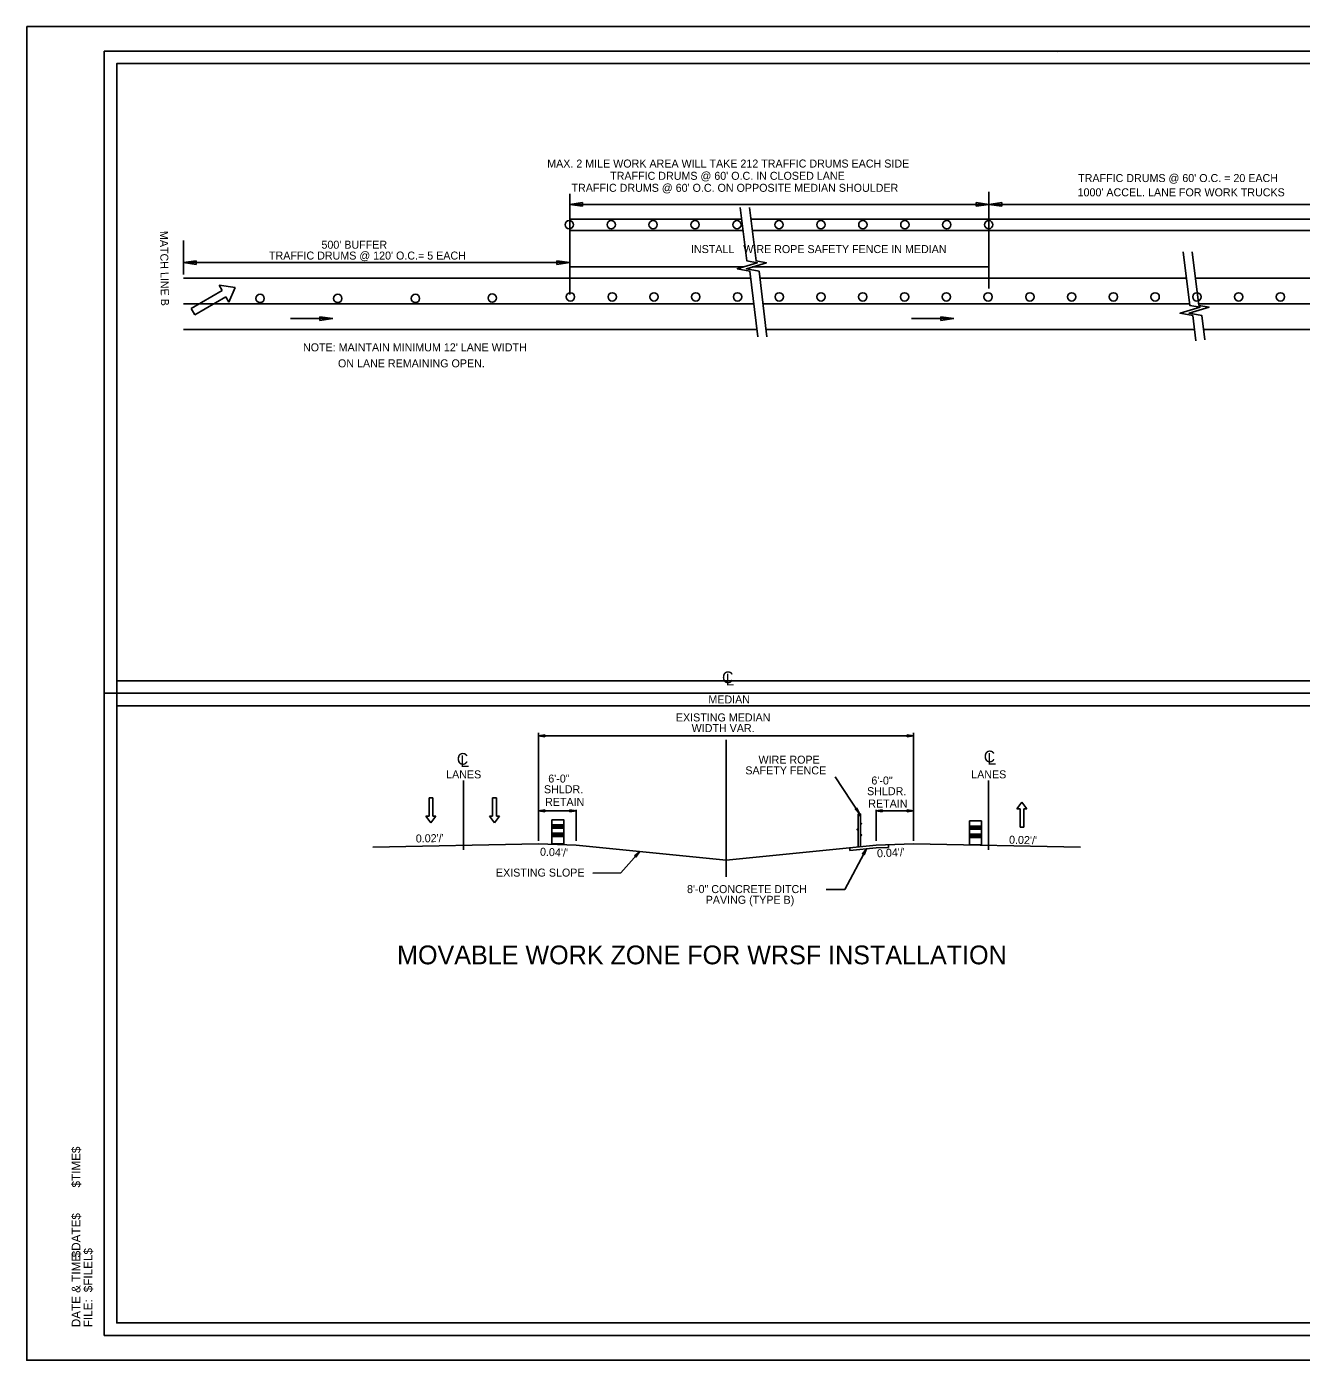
# Model space of a CAD drawing. Extents: x 1373222 to 1374279, y 380783 to 380996.
# Drawn here: x 1373945.4 to 1374149.3, y 380783.1 to 380996.5 of the extents above; entities that cross this region are included whole.
import ezdxf

# ---------------------------------------------------------------- set-up
doc = ezdxf.new("R2010")
doc.units = 0
for name, color, linetype in [('R_Border', 7, 'Continuous'), ('R_Border Notes', 7, 'Continuous'), ('R_Border Plan-Plan', 7, 'Continuous'), ('R_Draft', 7, 'Continuous'), ('R_No Plot', 7, 'Continuous')]:
    doc.layers.add(name, color=color, linetype=linetype)

msp = doc.modelspace()

# ---------------------------------------------------------------- linework, layer by layer
at = {"layer": 'R_Border'}
for p, q in [((1373957.81, 380992.59), (1374273.99, 380992.59)), ((1373957.81, 380787.13), (1373957.81, 380992.59)), ((1374110.33, 380992.33), (1374110.33, 380992.33)), ((1374110.33, 380992.33), (1374110.33, 380992.33)), ((1373957.81, 380787.13), (1373957.81, 380787.13)), ((1374273.99, 380787.13), (1373957.81, 380787.13))]:
    msp.add_line(p, q, dxfattribs=at)
at = {"layer": 'R_Border Plan-Plan'}
msp.add_line((1373957.81, 380889.86), (1374273.99, 380889.86), dxfattribs=at)
at = {"layer": 'R_Draft'}
for p, q in [((1374032.3, 380969.76), (1374032.3, 380953.63)), ((1374099.37, 380970.08), (1374099.37, 380954.63)), ((1374032.3, 380968.06), (1374034.36, 380968.37)), ((1374099.37, 380968.06), (1374032.3, 380968.06)), ((1374034.36, 380967.75), (1374032.3, 380968.06)), ((1374034.36, 380968.37), (1374034.36, 380967.75)), ((1374097.31, 380967.75), (1374097.31, 380968.37)), ((1374097.31, 380968.37), (1374099.37, 380968.06)), ((1374099.37, 380968.06), (1374097.31, 380967.75)), ((1374099.37, 380968.06), (1374101.43, 380968.37)), ((1374161.19, 380968.06), (1374099.37, 380968.06)), ((1374101.43, 380967.75), (1374099.37, 380968.06)), ((1374101.43, 380968.37), (1374101.43, 380967.75)), ((1374032.3, 380965.67), (1374059.82, 380965.67)), ((1374061.27, 380965.67), (1374167.51, 380965.67)), ((1374032.3, 380963.9), (1374060.04, 380963.9)), ((1374032.3, 380963.84), (1374032.3, 380953.63)), ((1374032.3, 380963.84), (1374032.3, 380953.63)), ((1374032.3, 380963.84), (1374032.3, 380953.63)), ((1374061.49, 380963.9), (1374167.5, 380963.9)), ((1373970.48, 380962.27), (1373970.48, 380956.85)), ((1373970.48, 380958.74), (1373972.54, 380959.05)), ((1374032.3, 380958.74), (1373970.48, 380958.74)), ((1373972.54, 380958.43), (1373970.48, 380958.74)), ((1373972.54, 380959.05), (1373972.54, 380958.43)), ((1374030.24, 380958.43), (1374030.24, 380959.05)), ((1374030.24, 380959.05), (1374032.3, 380958.74)), ((1374032.3, 380958.74), (1374030.24, 380958.43)), ((1374032.3, 380958.05), (1374060.04, 380958.05)), ((1374061.5, 380958.05), (1374099.37, 380958.05)), ((1373970.52, 380956.27), (1374032.3, 380956.27)), ((1373976.2, 380955.13), (1373976.69, 380954.29)), ((1373976.2, 380955.13), (1373978.74, 380954.79)), ((1374032.3, 380956.27), (1374061.26, 380956.27)), ((1374062.72, 380956.27), (1374099.37, 380956.27)), ((1374099.37, 380956.27), (1374130.94, 380956.27)), ((1374132.4, 380956.27), (1374168.15, 380956.27)), ((1373976.69, 380954.29), (1373971.7, 380951.41)), ((1373977.28, 380953.27), (1373972.29, 380950.39)), ((1373977.28, 380953.27), (1373977.76, 380952.42)), ((1373978.74, 380954.79), (1373977.76, 380952.42)), ((1373970.48, 380952.15), (1374032.3, 380952.15)), ((1373971.7, 380951.41), (1373972.29, 380950.39)), ((1374032.3, 380952.15), (1374061.76, 380952.15)), ((1374063.22, 380952.15), (1374099.37, 380952.15)), ((1374099.37, 380952.15), (1374131.46, 380952.15)), ((1374132.92, 380952.15), (1374168.15, 380952.15)), ((1373994.38, 380949.78), (1373987.62, 380949.78)), ((1373992.32, 380949.47), (1373992.32, 380950.08)), ((1373992.32, 380950.08), (1373994.38, 380949.78)), ((1373994.38, 380949.78), (1373992.32, 380949.47)), ((1374093.73, 380949.78), (1374086.97, 380949.78)), ((1374091.67, 380949.47), (1374091.67, 380950.08)), ((1374091.67, 380950.08), (1374093.73, 380949.78)), ((1374093.73, 380949.78), (1374091.67, 380949.47)), ((1373970.48, 380948.03), (1374032.3, 380948.03)), ((1374032.3, 380948.03), (1374062.26, 380948.03)), ((1374063.71, 380948.03), (1374099.37, 380948.03)), ((1374099.37, 380948.03), (1374132.24, 380948.03)), ((1374133.7, 380948.03), (1374168.15, 380948.03)), ((1374027.3, 380883.55), (1374027.3, 380866.27)), ((1374028.3, 380883.19), (1374027.3, 380883.04)), ((1374027.3, 380883.04), (1374087.3, 380883.04)), ((1374028.3, 380882.89), (1374027.3, 380883.04)), ((1374028.3, 380883.17), (1374027.46, 380883.04)), ((1374028.3, 380882.92), (1374027.46, 380883.04)), ((1374028.3, 380883.14), (1374027.63, 380883.04)), ((1374028.3, 380882.94), (1374027.63, 380883.04)), ((1374028.3, 380883.12), (1374027.8, 380883.04)), ((1374028.3, 380882.97), (1374027.8, 380883.04)), ((1374028.3, 380883.09), (1374027.97, 380883.04)), ((1374028.3, 380882.99), (1374027.97, 380883.04)), ((1374028.3, 380883.07), (1374028.14, 380883.04)), ((1374028.3, 380883.02), (1374028.14, 380883.04)), ((1374028.3, 380882.89), (1374028.3, 380883.19)), ((1374057.3, 380882.38), (1374057.3, 380860.5)), ((1374086.3, 380883.19), (1374087.3, 380883.04)), ((1374086.3, 380883.19), (1374086.3, 380882.89)), ((1374086.3, 380883.17), (1374087.13, 380883.04)), ((1374086.3, 380883.14), (1374086.96, 380883.04)), ((1374086.3, 380883.12), (1374086.79, 380883.04)), ((1374086.3, 380883.09), (1374086.62, 380883.04)), ((1374086.3, 380883.07), (1374086.46, 380883.04)), ((1374086.3, 380882.89), (1374087.3, 380883.04)), ((1374086.3, 380882.99), (1374086.62, 380883.04)), ((1374086.3, 380882.94), (1374086.96, 380883.04)), ((1374086.3, 380882.92), (1374087.13, 380883.04)), ((1374086.3, 380882.97), (1374086.79, 380883.04)), ((1374086.3, 380883.02), (1374086.46, 380883.04)), ((1374087.3, 380883.55), (1374087.3, 380879.16)), ((1374087.3, 380879.16), (1374087.3, 380866.27)), ((1374015.3, 380875.92), (1374015.3, 380864.79)), ((1374074.78, 380876.48), (1374078.64, 380870.58)), ((1374099.3, 380875.92), (1374099.3, 380864.79)), ((1374009.78, 380870.19), (1374009.78, 380873.13)), ((1374010.38, 380873.13), (1374009.78, 380873.13)), ((1374010.38, 380870.19), (1374010.38, 380873.13)), ((1374019.96, 380870.19), (1374019.96, 380873.13)), ((1374020.56, 380873.13), (1374019.96, 380873.13)), ((1374020.56, 380870.19), (1374020.56, 380873.13)), ((1374103.85, 380871.39), (1374104.65, 380872.42)), ((1374104.65, 380872.42), (1374105.45, 380871.39)), ((1374009.78, 380870.19), (1374009.28, 380870.19)), ((1374010.08, 380869.15), (1374009.28, 380870.19)), ((1374010.88, 380870.19), (1374010.08, 380869.15)), ((1374010.88, 380870.19), (1374010.38, 380870.19)), ((1374019.96, 380870.19), (1374019.46, 380870.19)), ((1374020.26, 380869.15), (1374019.46, 380870.19)), ((1374021.06, 380870.19), (1374020.26, 380869.15)), ((1374021.06, 380870.19), (1374020.56, 380870.19)), ((1374028.3, 380871.19), (1374027.3, 380871.04)), ((1374027.3, 380871.04), (1374033.3, 380871.04)), ((1374028.3, 380870.89), (1374027.3, 380871.04)), ((1374028.3, 380871.17), (1374027.46, 380871.04)), ((1374028.3, 380870.92), (1374027.46, 380871.04)), ((1374028.3, 380871.14), (1374027.64, 380871.04)), ((1374028.3, 380870.94), (1374027.64, 380871.04)), ((1374028.3, 380871.12), (1374027.8, 380871.04)), ((1374028.3, 380870.97), (1374027.8, 380871.04)), ((1374028.3, 380871.09), (1374027.97, 380871.04)), ((1374028.3, 380870.99), (1374027.97, 380871.04)), ((1374028.3, 380871.07), (1374028.14, 380871.04)), ((1374028.3, 380871.02), (1374028.14, 380871.04)), ((1374028.3, 380870.89), (1374028.3, 380871.19)), ((1374032.3, 380871.19), (1374033.3, 380871.04)), ((1374032.3, 380871.19), (1374032.3, 380870.89)), ((1374032.3, 380871.17), (1374033.13, 380871.04)), ((1374032.3, 380871.14), (1374032.96, 380871.04)), ((1374032.3, 380871.12), (1374032.79, 380871.04)), ((1374032.3, 380871.09), (1374032.62, 380871.04)), ((1374032.3, 380871.06), (1374032.45, 380871.04)), ((1374032.3, 380870.89), (1374033.3, 380871.04)), ((1374032.3, 380870.99), (1374032.62, 380871.04)), ((1374032.3, 380870.94), (1374032.96, 380871.04)), ((1374032.3, 380870.92), (1374033.13, 380871.04)), ((1374032.3, 380870.97), (1374032.79, 380871.04)), ((1374032.3, 380871.02), (1374032.45, 380871.04)), ((1374033.3, 380871.22), (1374033.3, 380866.27)), ((1374078.22, 380871.5), (1374077.97, 380871.33)), ((1374077.97, 380871.33), (1374078.64, 380870.58)), ((1374077.99, 380871.35), (1374078.55, 380870.72)), ((1374078.01, 380871.36), (1374078.45, 380870.86)), ((1374078.03, 380871.37), (1374078.36, 380871)), ((1374078.05, 380871.39), (1374078.27, 380871.14)), ((1374078.07, 380871.4), (1374078.18, 380871.28)), ((1374078.11, 380871.43), (1374078.18, 380871.28)), ((1374078.13, 380871.44), (1374078.27, 380871.14)), ((1374078.15, 380871.46), (1374078.36, 380871)), ((1374078.18, 380871.47), (1374078.45, 380870.86)), ((1374078.2, 380871.48), (1374078.55, 380870.72)), ((1374078.22, 380871.5), (1374078.64, 380870.58)), ((1374078.45, 380870.58), (1374078.83, 380870.58)), ((1374078.45, 380870.58), (1374078.45, 380865.27)), ((1374078.83, 380870.58), (1374078.83, 380865.3)), ((1374081.3, 380871.22), (1374081.3, 380866.27)), ((1374082.3, 380871.19), (1374081.3, 380871.04)), ((1374081.3, 380871.04), (1374087.3, 380871.04)), ((1374082.3, 380870.89), (1374081.3, 380871.04)), ((1374082.3, 380871.17), (1374081.47, 380871.04)), ((1374082.3, 380870.92), (1374081.47, 380871.04)), ((1374082.3, 380871.14), (1374081.64, 380871.04)), ((1374082.3, 380870.94), (1374081.64, 380871.04)), ((1374082.3, 380871.12), (1374081.81, 380871.04)), ((1374082.3, 380870.97), (1374081.81, 380871.04)), ((1374082.3, 380871.09), (1374081.98, 380871.04)), ((1374082.3, 380870.99), (1374081.98, 380871.04)), ((1374082.3, 380871.06), (1374082.14, 380871.04)), ((1374082.3, 380871.02), (1374082.14, 380871.04)), ((1374082.3, 380870.89), (1374082.3, 380871.19)), ((1374086.3, 380871.19), (1374087.3, 380871.04)), ((1374086.3, 380871.19), (1374086.3, 380870.89)), ((1374086.3, 380871.17), (1374087.13, 380871.04)), ((1374086.3, 380871.14), (1374086.96, 380871.04)), ((1374086.3, 380871.12), (1374086.8, 380871.04)), ((1374086.3, 380871.09), (1374086.63, 380871.04)), ((1374086.3, 380871.07), (1374086.46, 380871.04)), ((1374086.3, 380870.89), (1374087.3, 380871.04)), ((1374086.3, 380870.99), (1374086.63, 380871.04)), ((1374086.3, 380870.94), (1374086.96, 380871.04)), ((1374086.3, 380870.92), (1374087.13, 380871.04)), ((1374086.3, 380870.97), (1374086.8, 380871.04)), ((1374086.3, 380871.02), (1374086.46, 380871.04)), ((1374103.85, 380871.39), (1374104.35, 380871.39)), ((1374104.35, 380871.39), (1374104.35, 380868.44)), ((1374104.95, 380871.39), (1374104.95, 380868.44)), ((1374104.95, 380871.39), (1374105.45, 380871.39)), ((1374029.43, 380868.8), (1374031.35, 380868.8)), ((1374029.43, 380868.73), (1374031.35, 380868.73)), ((1374029.43, 380868.66), (1374031.35, 380868.66)), ((1374029.43, 380868.59), (1374031.35, 380868.59)), ((1374029.43, 380868.52), (1374031.35, 380868.52)), ((1374029.43, 380868.42), (1374031.35, 380868.42)), ((1374029.43, 380868.34), (1374031.35, 380868.34)), ((1374029.43, 380868.28), (1374031.35, 380868.28)), ((1374029.43, 380867.48), (1374031.35, 380867.48)), ((1374029.43, 380867.41), (1374031.35, 380867.41)), ((1374096.25, 380868.61), (1374098.17, 380868.61)), ((1374096.25, 380868.54), (1374098.17, 380868.54)), ((1374096.25, 380868.47), (1374098.17, 380868.47)), ((1374096.25, 380868.41), (1374098.17, 380868.41)), ((1374096.25, 380868.33), (1374098.17, 380868.33)), ((1374096.25, 380868.24), (1374098.17, 380868.24)), ((1374096.25, 380868.15), (1374098.17, 380868.15)), ((1374096.25, 380868.1), (1374098.17, 380868.1)), ((1374104.35, 380868.44), (1374104.95, 380868.44)), ((1374027.3, 380865.79), (1374000.77, 380865.26)), ((1374033.3, 380865.55), (1374027.3, 380865.79)), ((1374029.43, 380867.34), (1374031.35, 380867.34)), ((1374029.43, 380867.28), (1374031.35, 380867.28)), ((1374029.43, 380867.2), (1374031.35, 380867.2)), ((1374029.43, 380867.11), (1374031.35, 380867.11)), ((1374029.43, 380867.02), (1374031.35, 380867.02)), ((1374029.43, 380866.97), (1374031.35, 380866.97)), ((1374033.3, 380865.55), (1374057.3, 380863.15)), ((1374081.3, 380865.55), (1374057.3, 380863.15)), ((1374081.3, 380865.55), (1374087.3, 380865.79)), ((1374083.3, 380865.63), (1374083.3, 380865.19)), ((1374087.3, 380865.79), (1374113.99, 380865.26)), ((1374096.25, 380867.3), (1374098.17, 380867.3)), ((1374096.25, 380867.23), (1374098.17, 380867.23)), ((1374096.25, 380867.15), (1374098.17, 380867.15)), ((1374096.25, 380867.09), (1374098.17, 380867.09)), ((1374096.25, 380867.01), (1374098.17, 380867.01)), ((1374096.25, 380866.92), (1374098.17, 380866.92)), ((1374096.25, 380866.83), (1374098.17, 380866.83)), ((1374096.25, 380866.78), (1374098.17, 380866.78)), ((1374040.48, 380861.13), (1374043.44, 380864.5)), ((1374042.67, 380863.85), (1374043.44, 380864.5)), ((1374042.67, 380863.85), (1374042.89, 380863.65)), ((1374042.69, 380863.83), (1374043.33, 380864.38)), ((1374042.71, 380863.82), (1374043.22, 380864.25)), ((1374042.72, 380863.8), (1374043.11, 380864.12)), ((1374042.74, 380863.78), (1374043, 380864)), ((1374042.76, 380863.77), (1374042.89, 380863.87)), ((1374042.8, 380863.74), (1374042.89, 380863.87)), ((1374042.82, 380863.72), (1374043, 380864)), ((1374042.84, 380863.7), (1374043.11, 380864.12)), ((1374042.86, 380863.69), (1374043.22, 380864.25)), ((1374042.87, 380863.67), (1374043.33, 380864.38)), ((1374042.89, 380863.65), (1374043.44, 380864.5)), ((1374076.31, 380858.44), (1374079.75, 380864.95)), ((1374077.09, 380865.13), (1374077.09, 380864.68)), ((1374081.3, 380865.11), (1374077.09, 380864.68)), ((1374079.13, 380864.15), (1374079.75, 380864.95)), ((1374079.13, 380864.15), (1374079.39, 380864)), ((1374079.15, 380864.14), (1374079.67, 380864.8)), ((1374079.18, 380864.12), (1374079.58, 380864.65)), ((1374079.2, 380864.11), (1374079.5, 380864.51)), ((1374079.22, 380864.1), (1374079.42, 380864.36)), ((1374079.24, 380864.09), (1374079.34, 380864.21)), ((1374079.28, 380864.06), (1374079.34, 380864.21)), ((1374079.31, 380864.05), (1374079.42, 380864.36)), ((1374079.33, 380864.04), (1374079.5, 380864.51)), ((1374079.35, 380864.03), (1374079.58, 380864.65)), ((1374079.37, 380864.02), (1374079.67, 380864.8)), ((1374079.39, 380864), (1374079.75, 380864.95)), ((1374083.3, 380865.19), (1374081.3, 380865.11)), ((1374035.97, 380861.08), (1374040.48, 380861.13)), ((1374076.31, 380858.44), (1374073.31, 380858.44))]:
    msp.add_line(p, q, dxfattribs=at)
for points in [[(1374059.58, 380967.58), (1374060.65, 380959.02), (1374062.3, 380958.73), (1374059.09, 380957.76), (1374061.13, 380957.37), (1374062.39, 380946.88)], [(1374061.03, 380967.58), (1374062.1, 380959.02), (1374063.75, 380958.73), (1374060.55, 380957.76), (1374062.59, 380957.37), (1374063.85, 380946.88)], [(1374130.42, 380960.46), (1374131.49, 380951.91), (1374133.14, 380951.62), (1374129.94, 380950.64), (1374131.98, 380950.26), (1374132.46, 380946.24)], [(1374131.88, 380960.46), (1374132.95, 380951.91), (1374134.6, 380951.62), (1374131.39, 380950.64), (1374133.43, 380950.26), (1374133.89, 380946.41)]]:
    msp.add_lwpolyline(points, dxfattribs=at)
for points in [[(1374029.43, 380869.62), (1374031.35, 380869.62), (1374031.35, 380865.78), (1374029.43, 380865.78)], [(1374096.25, 380869.43), (1374098.17, 380869.43), (1374098.17, 380865.59), (1374096.25, 380865.59)]]:
    msp.add_lwpolyline(points, close=True, dxfattribs=at)
for centre, radius in [((1374032.22, 380964.81), 0.667), ((1374038.93, 380964.81), 0.667), ((1374045.64, 380964.81), 0.667), ((1374052.35, 380964.81), 0.667), ((1374059.06, 380964.81), 0.667), ((1374065.77, 380964.81), 0.667), ((1374072.48, 380964.81), 0.667), ((1374079.19, 380964.81), 0.667), ((1374085.91, 380964.81), 0.667), ((1374092.62, 380964.81), 0.667), ((1374099.33, 380964.81), 0.667), ((1373982.75, 380953.02), 0.667), ((1373995.18, 380953.02), 0.667), ((1374007.6, 380953.02), 0.667), ((1374019.9, 380953.08), 0.667), ((1374032.41, 380953.26), 0.667), ((1374039.09, 380953.26), 0.667), ((1374045.77, 380953.26), 0.667), ((1374052.46, 380953.26), 0.667), ((1374059.14, 380953.26), 0.667), ((1374065.82, 380953.26), 0.667), ((1374072.5, 380953.26), 0.667), ((1374079.18, 380953.26), 0.667), ((1374085.87, 380953.26), 0.667), ((1374092.55, 380953.26), 0.667), ((1374099.23, 380953.26), 0.667), ((1374099.23, 380953.26), 0.667), ((1374105.91, 380953.26), 0.667), ((1374112.6, 380953.26), 0.667), ((1374119.28, 380953.26), 0.667), ((1374125.96, 380953.26), 0.667), ((1374132.64, 380953.26), 0.667), ((1374139.32, 380953.26), 0.667), ((1374146.01, 380953.26), 0.667), ((1374078.64, 380870.33), 0.0683), ((1374078.33, 380868.06), 0.0683), ((1374078.92, 380869), 0.0683), ((1374078.94, 380867.17), 0.0683)]:
    msp.add_circle(centre, radius, dxfattribs=at)
at = {"layer": 'R_No Plot'}
for points in [[(1373945.41, 380996.49), (1374278.75, 380996.49), (1374278.75, 380783.15), (1373945.41, 380783.15)], [(1374271.99, 380891.86), (1373959.81, 380891.86), (1373959.81, 380990.59), (1374209.35, 380990.59), (1374209.35, 380980.71), (1374226.89, 380980.71), (1374250.99, 380980.71), (1374250.99, 380958.38), (1374271.99, 380958.38)], [(1373959.81, 380990.59), (1374209.35, 380990.59), (1374209.35, 380980.71), (1374226.89, 380980.71), (1374250.99, 380980.71), (1374250.99, 380958.38), (1374271.99, 380958.38), (1374271.99, 380789.13), (1373959.81, 380789.13)], [(1373959.81, 380887.86), (1374271.99, 380887.86), (1374271.99, 380789.13), (1373959.81, 380789.13)]]:
    msp.add_lwpolyline(points, close=True, dxfattribs=at)

# ---------------------------------------------------------------- texts
at = {"layer": 'R_Border Notes'}
for s, height, p in [('$TIME$', 1.397, (1373954.01, 380810.8)), ('$DATE$', 1.397, (1373954.01, 380799.63)), ('DATE & TIME:', 1.3968, (1373954.01, 380788.45)), ('$FILEL$', 1.397, (1373955.93, 380794.04)), ('FILE: ', 1.397, (1373955.93, 380788.45))]:
    msp.add_text(s, height=height, rotation=90, dxfattribs=at).set_placement(p)
at = {"layer": 'R_Draft'}
for s, height, p in [('MAX. 2 MILE WORK AREA WILL TAKE 212 TRAFFIC DRUMS EACH SIDE', 1.28, (1374028.69, 380973.95)), ("TRAFFIC DRUMS @ 60' O.C. IN CLOSED LANE", 1.28, (1374038.76, 380971.99)), ("TRAFFIC DRUMS @ 60' O.C. = 20 EACH", 1.28, (1374113.64, 380971.63)), ("TRAFFIC DRUMS @ 60' O.C. ON OPPOSITE MEDIAN SHOULDER", 1.28, (1374032.58, 380970.07)), ("1000' ACCEL. LANE FOR WORK TRUCKS", 1.28, (1374113.55, 380969.35)), ("500' BUFFER", 1.28, (1373992.57, 380960.97)), ('INSTALL   WIRE ROPE SAFETY FENCE IN MEDIAN', 1.28, (1374051.69, 380960.27)), ("TRAFFIC DRUMS @ 120' O.C.= 5 EACH", 1.28, (1373984.18, 380959.23)), ("NOTE: MAINTAIN MINIMUM 12' LANE WIDTH", 1.28, (1373989.62, 380944.55)), (' ON LANE REMAINING OPEN.', 1.28, (1373994.74, 380941.99)), ('C', 1.88, (1374056.66, 380891.47)), ('L', 1.88, (1374057.23, 380891.1)), ('MEDIAN', 1.28, (1374054.48, 380888.22)), ('EXISTING MEDIAN', 1.28, (1374049.28, 380885.35)), ('WIDTH VAR.', 1.28, (1374051.8, 380883.64)), ('C', 1.88, (1374014.23, 380878.42)), ('C', 1.88, (1374098.54, 380878.8)), ('L', 1.88, (1374099.11, 380878.43)), ('L', 1.88, (1374014.8, 380878.06)), ('SAFETY FENCE', 1.28, (1374060.39, 380876.88)), ('WIRE ROPE', 1.28, (1374062.5, 380878.59)), ('LANES', 1.28, (1374012.52, 380876.24)), ('6\'-0"', 1.28, (1374028.86, 380875.57)), ('6\'-0"', 1.28, (1374080.56, 380875.26)), ('LANES', 1.28, (1374096.53, 380876.24)), ('SHLDR.', 1.28, (1374028.17, 380873.86)), ('SHLDR.', 1.28, (1374079.87, 380873.55)), ('RETAIN', 1.28, (1374028.35, 380871.84)), ('RETAIN', 1.28, (1374080.06, 380871.57)), ('EXISTING SLOPE', 1.28, (1374020.49, 380860.53)), ('8\'-0" CONCRETE DITCH', 1.28, (1374051.06, 380857.89)), ('PAVING (TYPE B)', 1.28, (1374054.05, 380856.18)), ('MOVABLE WORK ZONE FOR WRSF INSTALLATION', 3.0041, (1374004.67, 380846.5))]:
    msp.add_text(s, height=height, dxfattribs=at).set_placement(p)
for s, rotation, p in [('MATCH LINE B', 270.8059, (1373966.73, 380963.8)), ("0.02'/'", 1.1458, (1374007.68, 380865.98)), ("0.02'/'", 358.4871, (1374102.57, 380865.8)), ("0.04'/'", 357.7799, (1374027.52, 380863.88)), ("0.04'/'", 3.0313, (1374081.49, 380863.6))]:
    msp.add_text(s, height=1.28, rotation=rotation, dxfattribs=at).set_placement(p)

doc.saveas('drawing.dxf')
